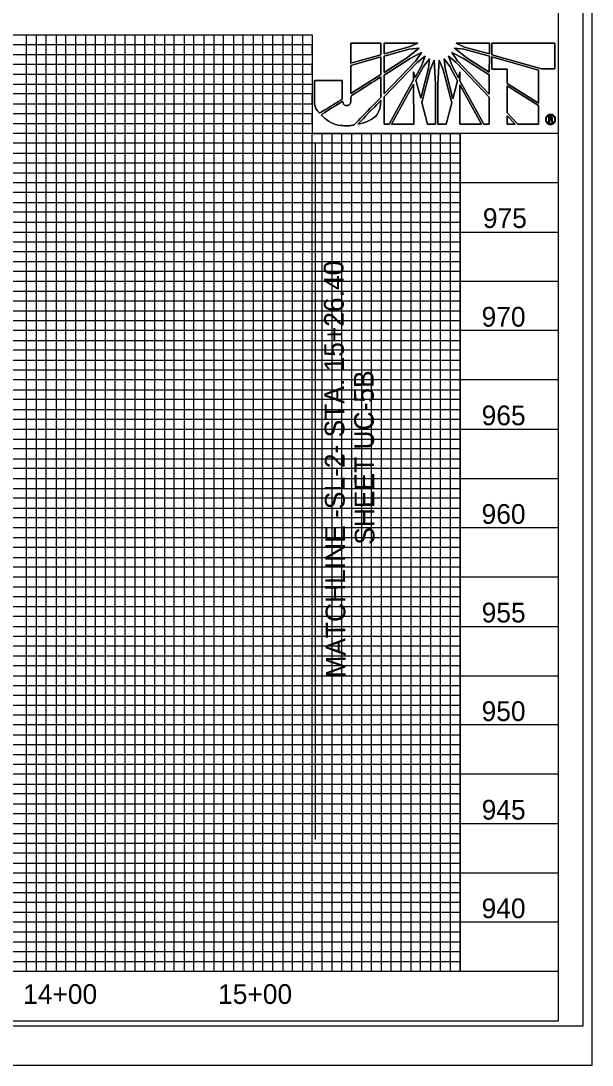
# Model space of a CAD drawing. Extents: x 0 to 2694, y -754 to 1499.
# Drawn here: x 2.35 to 2.833, y 0.008 to 0.891 of the extents above; entities that cross this region are included whole.
import ezdxf

# ---------------------------------------------------------------- set-up
doc = ezdxf.new("R2010")
doc.units = 0
for name, color, linetype in [('Layer 1', 7, 'Continuous'), ('Sheet Profile Grid Major CELL', 7, 'Continuous'), ('Sheet Profile Grid Middle', 7, 'Continuous'), ('Sheet Profile Grid Minor CELL', 7, 'Continuous'), ('UC Plan Profile Sheet 34 CELL', 7, 'Continuous'), ('UC Plan Sheet 34 CELL', 7, 'Continuous')]:
    doc.layers.add(name, color=color, linetype=linetype)

# ---------------------------------------------------------------- blocks, each defined once
blk = doc.blocks.new('block 2_1')
at = {"layer": 'Layer 1'}
for p, q in [((0.10682, 0.1325), (0.10682, 0.14026)), ((0.10682, 0.14026), (0.11852, 0.14026)), ((0.11852, 0.14026), (0.11852, 0.13575)), ((0.11973, 0.13613), (0.11973, 0.14032)), ((0.11973, 0.14032), (0.1329, 0.14032)), ((0.12954, 0.13884), (0.11973, 0.13613)), ((0.13337, 0.13839), (0.12852, 0.13445)), ((0.1329, 0.14032), (0.12954, 0.13884)), ((0.12954, 0.13793), (0.13337, 0.13839)), ((0.14715, 0.13839), (0.15076, 0.13793)), ((0.15206, 0.13438), (0.14715, 0.13839)), ((0.15109, 0.13878), (0.14781, 0.14032)), ((0.14781, 0.14032), (0.16078, 0.14026)), ((0.16078, 0.13606), (0.15109, 0.13878)), ((0.16078, 0.14026), (0.16078, 0.13606)), ((0.16169, 0.1358), (0.16169, 0.14032)), ((0.16169, 0.14032), (0.18629, 0.14032)), ((0.18629, 0.14032), (0.18629, 0.13024)), ((0.11852, 0.13575), (0.10682, 0.1325)), ((0.10682, 0.13161), (0.11852, 0.1349)), ((0.11852, 0.1349), (0.11852, 0.12812)), ((0.11973, 0.13523), (0.12954, 0.13793)), ((0.11973, 0.12889), (0.11973, 0.13523)), ((0.12852, 0.13445), (0.11973, 0.12889)), ((0.11973, 0.12787), (0.12987, 0.13432)), ((0.12987, 0.13432), (0.13433, 0.13658)), ((0.13433, 0.13658), (0.13207, 0.13341)), ((0.13257, 0.13277), (0.13568, 0.13517)), ((0.13568, 0.13517), (0.13425, 0.13142)), ((0.14476, 0.13517), (0.14787, 0.13277)), ((0.14619, 0.13142), (0.14476, 0.13517)), ((0.14613, 0.13658), (0.15065, 0.13432)), ((0.14839, 0.13335), (0.14613, 0.13658)), ((0.15065, 0.13432), (0.16071, 0.12793)), ((0.15076, 0.13793), (0.16078, 0.13517)), ((0.16071, 0.12897), (0.15206, 0.13438)), ((0.16078, 0.13517), (0.16071, 0.12897)), ((0.16169, 0.13567), (0.16169, 0.1358)), ((0.18106, 0.13024), (0.16169, 0.13567)), ((0.16169, 0.13497), (0.17982, 0.1298)), ((0.16169, 0.1349), (0.16169, 0.13497)), ((0.16169, 0.13019), (0.16169, 0.1349)), ((0.10682, 0.12071), (0.10682, 0.13161)), ((0.13207, 0.13341), (0.11973, 0.12057)), ((0.11973, 0.11933), (0.13257, 0.13277)), ((0.13425, 0.13142), (0.1318, 0.12696)), ((0.13213, 0.12586), (0.13505, 0.13115)), ((0.13704, 0.13051), (0.134, 0.11883)), ((0.13505, 0.13115), (0.13736, 0.13412)), ((0.13736, 0.13412), (0.13704, 0.13051)), ((0.13769, 0.12986), (0.13929, 0.1336)), ((0.13929, 0.1336), (0.1398, 0.12437)), ((0.14063, 0.12437), (0.14123, 0.1336)), ((0.14123, 0.1336), (0.14277, 0.12986)), ((0.1431, 0.13412), (0.14536, 0.13115)), ((0.14348, 0.13038), (0.1431, 0.13412)), ((0.14652, 0.11856), (0.14348, 0.13038)), ((0.14536, 0.13115), (0.14839, 0.12567)), ((0.1487, 0.12677), (0.14619, 0.13142)), ((0.14787, 0.13277), (0.16071, 0.11922)), ((0.16071, 0.12043), (0.14839, 0.13335)), ((0.1677, 0.13019), (0.16169, 0.13019)), ((0.1677, 0.12457), (0.1677, 0.13019)), ((0.18629, 0.13024), (0.18106, 0.13024)), ((0.11852, 0.12812), (0.10682, 0.12071)), ((0.11973, 0.12057), (0.11973, 0.12787)), ((0.1318, 0.12696), (0.13122, 0.12908)), ((0.13122, 0.12908), (0.13122, 0.126)), ((0.13439, 0.11721), (0.13769, 0.12986)), ((0.14277, 0.12986), (0.14613, 0.11702)), ((0.1493, 0.12908), (0.1487, 0.12677)), ((0.1493, 0.12567), (0.1493, 0.12908)), ((0.16071, 0.12793), (0.16071, 0.12043)), ((0.17982, 0.1298), (0.17982, 0.11688)), ((0.13122, 0.126), (0.12167, 0.10871)), ((0.12257, 0.10871), (0.13122, 0.12432)), ((0.13122, 0.12432), (0.1313, 0.10871)), ((0.134, 0.11883), (0.13213, 0.12586)), ((0.1398, 0.12437), (0.1398, 0.10877)), ((0.14063, 0.10877), (0.14063, 0.12437)), ((0.14839, 0.12567), (0.14652, 0.11856)), ((0.15864, 0.10871), (0.1493, 0.12567)), ((0.1493, 0.10877), (0.1493, 0.12399)), ((0.1493, 0.12399), (0.15768, 0.10877)), ((0.17982, 0.11688), (0.1677, 0.12457)), ((0.1677, 0.1236), (0.17982, 0.11597)), ((0.1677, 0.11314), (0.1677, 0.1236)), ((0.11973, 0.10871), (0.11973, 0.11933)), ((0.16071, 0.11922), (0.16071, 0.10871)), ((0.13659, 0.10877), (0.13439, 0.11721)), ((0.14613, 0.11702), (0.14387, 0.10877)), ((0.17982, 0.11597), (0.17982, 0.10871)), ((0.17189, 0.10871), (0.1677, 0.11314)), ((0.1677, 0.10871), (0.1677, 0.112)), ((0.1677, 0.112), (0.17073, 0.10871)), ((0.12167, 0.10871), (0.11973, 0.10871)), ((0.1313, 0.10871), (0.12257, 0.10871)), ((0.1398, 0.10877), (0.13659, 0.10877)), ((0.14387, 0.10877), (0.14063, 0.10877)), ((0.15768, 0.10877), (0.1493, 0.10877)), ((0.16071, 0.10871), (0.15864, 0.10871)), ((0.17073, 0.10871), (0.1677, 0.10871)), ((0.17982, 0.10871), (0.17189, 0.10871))]:
    blk.add_line(p, q, dxfattribs=at)
for points in [[(0.10682, 0.1325), (0.11852, 0.13575), (0.11852, 0.14026), (0.10682, 0.14026), (0.10682, 0.1325)], [(0.12954, 0.13884), (0.1329, 0.14032), (0.11973, 0.14032), (0.11973, 0.13613), (0.12954, 0.13884)], [(0.11973, 0.13523), (0.11973, 0.12889), (0.12852, 0.13445), (0.13337, 0.13839), (0.12954, 0.13793), (0.11973, 0.13523)], [(0.14715, 0.13839), (0.15206, 0.13438), (0.16071, 0.12897), (0.16078, 0.13517), (0.15076, 0.13793), (0.14715, 0.13839)], [(0.15109, 0.13878), (0.16078, 0.13606), (0.16078, 0.14026), (0.14781, 0.14032), (0.15109, 0.13878)], [(0.18629, 0.14032), (0.16169, 0.14032), (0.16169, 0.1358), (0.16169, 0.13567), (0.18106, 0.13024), (0.18629, 0.13024), (0.18629, 0.14032)], [(0.10682, 0.12071), (0.11852, 0.12812), (0.11852, 0.1349), (0.10682, 0.13161), (0.10682, 0.12071)], [(0.11973, 0.12787), (0.11973, 0.12057), (0.13207, 0.13341), (0.13433, 0.13658), (0.12987, 0.13432), (0.11973, 0.12787)], [(0.13568, 0.13517), (0.13257, 0.13277), (0.11973, 0.11933), (0.11973, 0.10871), (0.12167, 0.10871), (0.13122, 0.126), (0.13122, 0.12908), (0.1318, 0.12696), (0.13425, 0.13142), (0.13568, 0.13517)], [(0.14476, 0.13517), (0.14619, 0.13142), (0.1487, 0.12677), (0.1493, 0.12908), (0.1493, 0.12567), (0.15864, 0.10871), (0.16071, 0.10871), (0.16071, 0.11922), (0.14787, 0.13277), (0.14476, 0.13517)], [(0.14613, 0.13658), (0.14839, 0.13335), (0.16071, 0.12043), (0.16071, 0.12793), (0.15065, 0.13432), (0.14613, 0.13658)], [(0.16169, 0.13497), (0.16169, 0.1349), (0.16169, 0.13019), (0.1677, 0.13019), (0.1677, 0.12457), (0.17982, 0.11688), (0.17982, 0.1298), (0.16169, 0.13497)], [(0.13736, 0.13412), (0.13505, 0.13115), (0.13213, 0.12586), (0.134, 0.11883), (0.13704, 0.13051), (0.13736, 0.13412)], [(0.13769, 0.12986), (0.13439, 0.11721), (0.13659, 0.10877), (0.1398, 0.10877), (0.1398, 0.12437), (0.13929, 0.1336), (0.13769, 0.12986)], [(0.14123, 0.1336), (0.14063, 0.12437), (0.14063, 0.10877), (0.14387, 0.10877), (0.14613, 0.11702), (0.14277, 0.12986), (0.14123, 0.1336)], [(0.1431, 0.13412), (0.14348, 0.13038), (0.14652, 0.11856), (0.14839, 0.12567), (0.14536, 0.13115), (0.1431, 0.13412)], [(0.12257, 0.10871), (0.1313, 0.10871), (0.13122, 0.12432), (0.12257, 0.10871)], [(0.1493, 0.10877), (0.15768, 0.10877), (0.1493, 0.12399), (0.1493, 0.10877)], [(0.1677, 0.1236), (0.1677, 0.11314), (0.17189, 0.10871), (0.17982, 0.10871), (0.17982, 0.11597), (0.1677, 0.1236), (0.1677, 0.1236)], [(0.1677, 0.10871), (0.1677, 0.10871), (0.17073, 0.10871), (0.1677, 0.112), (0.1677, 0.10871)], [(0.18456, 0.11147), (0.18383, 0.11147), (0.18383, 0.10968), (0.18424, 0.10968), (0.18424, 0.11038), (0.18456, 0.11038), (0.18456, 0.1107), (0.18424, 0.1107), (0.18424, 0.11113), (0.18456, 0.11113), (0.18456, 0.11147)], [(0.18456, 0.11147), (0.18383, 0.11147), (0.18383, 0.10968), (0.18424, 0.10968), (0.18424, 0.11038), (0.18456, 0.11038)], [(0.18456, 0.1107), (0.18424, 0.1107), (0.18424, 0.11113), (0.18456, 0.11113)]]:
    blk.add_lwpolyline(points, dxfattribs=at)
for points in [[(0.10514, 0.11597), (0.10444, 0.11597), (0.10384, 0.11636), (0.10359, 0.11765), (0.10359, 0.11765), (0.09519, 0.11246), (0.09519, 0.11246), (0.09778, 0.10974), (0.10191, 0.10812), (0.10541, 0.10812), (0.10632, 0.10812), (0.10701, 0.10819), (0.10798, 0.10839), (0.10798, 0.10839), (0.11852, 0.11928), (0.11852, 0.11928), (0.11852, 0.11928), (0.11852, 0.12715), (0.11852, 0.12715), (0.11852, 0.12715), (0.10682, 0.11972), (0.10682, 0.11972), (0.10682, 0.11677), (0.1061, 0.11597), (0.10514, 0.11597)], [(0.10514, 0.11597), (0.1061, 0.11597), (0.10682, 0.11677), (0.10682, 0.11972), (0.10682, 0.11972), (0.11852, 0.12715), (0.11852, 0.12715), (0.11852, 0.12715), (0.11852, 0.11928), (0.11852, 0.11928), (0.11852, 0.11928), (0.10798, 0.10839), (0.10798, 0.10839), (0.10701, 0.10819), (0.10632, 0.10812), (0.10541, 0.10812), (0.10191, 0.10812), (0.09778, 0.10974), (0.09519, 0.11246), (0.09519, 0.11246), (0.10359, 0.11765), (0.10359, 0.11765), (0.10384, 0.11636), (0.10444, 0.11597), (0.10514, 0.11597)], [(0.10346, 0.12573), (0.10346, 0.12573), (0.09263, 0.12573), (0.09263, 0.12573), (0.09263, 0.12573), (0.09263, 0.11895), (0.09263, 0.11895), (0.09263, 0.11895), (0.09263, 0.11823), (0.09263, 0.11823), (0.09263, 0.11611), (0.09332, 0.11443), (0.09456, 0.11302), (0.09456, 0.11302), (0.10346, 0.11843), (0.10346, 0.11856), (0.10346, 0.11856), (0.10346, 0.12573), (0.10346, 0.12573)], [(0.10346, 0.12573), (0.10346, 0.12573), (0.10346, 0.11856), (0.10346, 0.11856), (0.10346, 0.11843), (0.09456, 0.11302), (0.09456, 0.11302), (0.09332, 0.11443), (0.09263, 0.11611), (0.09263, 0.11823), (0.09263, 0.11823), (0.09263, 0.11895), (0.09263, 0.11895), (0.09263, 0.11895), (0.09263, 0.12573), (0.09263, 0.12573), (0.09263, 0.12573), (0.10346, 0.12573), (0.10346, 0.12573)], [(0.11852, 0.11804), (0.11852, 0.11804), (0.1094, 0.10864), (0.1094, 0.10864), (0.11386, 0.10974), (0.11831, 0.11269), (0.11852, 0.11804)], [(0.11852, 0.11804), (0.11831, 0.11269), (0.11386, 0.10974), (0.1094, 0.10864), (0.1094, 0.10864), (0.11852, 0.11804), (0.11852, 0.11804)], [(0.18456, 0.10859), (0.18403, 0.10859), (0.18355, 0.10878), (0.18316, 0.10917), (0.18277, 0.10955), (0.18258, 0.11002), (0.18258, 0.11057), (0.18258, 0.11113), (0.18277, 0.1116), (0.18316, 0.11195), (0.18355, 0.11233), (0.18401, 0.11252), (0.18456, 0.11252), (0.18456, 0.11252), (0.18456, 0.11215), (0.18456, 0.11215), (0.18412, 0.11215), (0.18375, 0.112), (0.18344, 0.11171), (0.18313, 0.1114), (0.18297, 0.11101), (0.18297, 0.11057), (0.18297, 0.11013), (0.18313, 0.10974), (0.18344, 0.10943), (0.18375, 0.10913), (0.18412, 0.10898), (0.18456, 0.10898), (0.18456, 0.10898), (0.18456, 0.10859), (0.18456, 0.10859), (0.18456, 0.10859), (0.18456, 0.10859), (0.18456, 0.10859)], [(0.18456, 0.11252), (0.18401, 0.11252), (0.18355, 0.11233), (0.18316, 0.11195), (0.18277, 0.1116), (0.18258, 0.11113), (0.18258, 0.11057), (0.18258, 0.11002), (0.18277, 0.10955), (0.18316, 0.10917), (0.18355, 0.10878), (0.18403, 0.10859), (0.18456, 0.10859)], [(0.18456, 0.10898), (0.18412, 0.10898), (0.18375, 0.10913), (0.18344, 0.10943), (0.18313, 0.10974), (0.18297, 0.11013), (0.18297, 0.11057), (0.18297, 0.11101), (0.18313, 0.1114), (0.18344, 0.11171), (0.18375, 0.112), (0.18412, 0.11215), (0.18456, 0.11215)], [(0.18656, 0.11057), (0.18656, 0.11002), (0.18637, 0.10955), (0.18599, 0.10916), (0.1856, 0.10878), (0.18513, 0.10859), (0.18458, 0.10859), (0.18458, 0.10859), (0.18458, 0.10859), (0.18456, 0.10859), (0.18456, 0.10859), (0.18456, 0.10898), (0.18456, 0.10898), (0.18458, 0.10898), (0.18458, 0.10898), (0.18458, 0.10898), (0.18502, 0.10898), (0.18539, 0.10913), (0.1857, 0.10943), (0.18601, 0.10974), (0.18617, 0.11013), (0.18617, 0.11057), (0.18617, 0.11101), (0.18601, 0.1114), (0.1857, 0.11171), (0.18539, 0.112), (0.18502, 0.11215), (0.18456, 0.11215), (0.18456, 0.11215), (0.18456, 0.11252), (0.18456, 0.11252), (0.18512, 0.11252), (0.18559, 0.11233), (0.18598, 0.11195), (0.18637, 0.1116), (0.18656, 0.11113), (0.18656, 0.11057), (0.18656, 0.11057), (0.18656, 0.11057), (0.18656, 0.11057)], [(0.18656, 0.11057), (0.18656, 0.11113), (0.18637, 0.1116), (0.18598, 0.11195), (0.18559, 0.11233), (0.18512, 0.11252), (0.18456, 0.11252)], [(0.18456, 0.11215), (0.18502, 0.11215), (0.18539, 0.112), (0.1857, 0.11171), (0.18601, 0.1114), (0.18617, 0.11101), (0.18617, 0.11057), (0.18617, 0.11013), (0.18601, 0.10974), (0.1857, 0.10943), (0.18539, 0.10913), (0.18502, 0.10898), (0.18458, 0.10898), (0.18458, 0.10898), (0.18458, 0.10898), (0.18456, 0.10898)], [(0.18456, 0.11038), (0.18456, 0.11038), (0.18456, 0.1107), (0.18456, 0.1107), (0.18456, 0.1107), (0.18458, 0.1107), (0.18458, 0.1107), (0.18484, 0.1107), (0.18497, 0.11078), (0.18497, 0.11093), (0.18497, 0.11106), (0.18485, 0.11113), (0.18461, 0.11113), (0.18461, 0.11113), (0.18456, 0.11113), (0.18456, 0.11113), (0.18456, 0.11113), (0.18456, 0.11147), (0.18456, 0.11147), (0.18456, 0.11147), (0.18468, 0.11147), (0.18468, 0.11147), (0.18513, 0.11147), (0.18536, 0.11129), (0.18536, 0.11093), (0.18536, 0.11077), (0.18529, 0.11064), (0.18515, 0.11054), (0.18526, 0.11048), (0.18533, 0.11033), (0.18534, 0.1101), (0.18534, 0.1101), (0.18534, 0.11), (0.18534, 0.11), (0.18534, 0.11), (0.18536, 0.10994), (0.18536, 0.10994), (0.18536, 0.10994), (0.18536, 0.10987), (0.18536, 0.10987), (0.18536, 0.10987), (0.18541, 0.10968), (0.18541, 0.10968), (0.18541, 0.10968), (0.18503, 0.10968), (0.18503, 0.10968), (0.18499, 0.10978), (0.18495, 0.10987), (0.18495, 0.11), (0.18495, 0.11017), (0.18494, 0.11026), (0.18489, 0.11031), (0.18484, 0.11034), (0.18474, 0.11038), (0.18458, 0.11038), (0.18458, 0.11038), (0.18456, 0.11038), (0.18456, 0.11038)], [(0.18456, 0.11038), (0.18456, 0.11038), (0.18458, 0.11038), (0.18458, 0.11038), (0.18474, 0.11038), (0.18484, 0.11034), (0.18489, 0.11031), (0.18494, 0.11026), (0.18495, 0.11017), (0.18495, 0.11), (0.18495, 0.10987), (0.18499, 0.10978), (0.18503, 0.10968), (0.18503, 0.10968), (0.18541, 0.10968), (0.18541, 0.10968), (0.18541, 0.10968), (0.18536, 0.10987), (0.18536, 0.10987), (0.18536, 0.10987), (0.18536, 0.10994), (0.18536, 0.10994), (0.18536, 0.10994), (0.18534, 0.11), (0.18534, 0.11), (0.18534, 0.11), (0.18534, 0.1101), (0.18534, 0.1101), (0.18533, 0.11033), (0.18526, 0.11048), (0.18515, 0.11054), (0.18529, 0.11064), (0.18536, 0.11077), (0.18536, 0.11093), (0.18536, 0.11129), (0.18513, 0.11147), (0.18468, 0.11147), (0.18468, 0.11147), (0.18456, 0.11147), (0.18456, 0.11147)], [(0.18456, 0.11113), (0.18456, 0.11113), (0.18461, 0.11113), (0.18461, 0.11113), (0.18485, 0.11113), (0.18497, 0.11106), (0.18497, 0.11093), (0.18497, 0.11078), (0.18484, 0.1107), (0.18458, 0.1107), (0.18458, 0.1107), (0.18456, 0.1107), (0.18456, 0.1107)], [(0.18456, 0.10859), (0.18458, 0.10859), (0.18458, 0.10859), (0.18458, 0.10859), (0.18513, 0.10859), (0.1856, 0.10878), (0.18599, 0.10916), (0.18637, 0.10955), (0.18656, 0.11002), (0.18656, 0.11057)]]:
    blk.add_open_spline(points, degree=3, dxfattribs=at)

msp = doc.modelspace()

# ---------------------------------------------------------------- linework, layer by layer
at = {"layer": 'Sheet Profile Grid Major CELL'}
for points in [[(0.30499, 0.87916), (2.59666, 0.87916)], [(2.38833, 0.0875), (2.38833, 0.87916), (2.47166, 0.87916), (2.47166, 0.0875)], [(2.55499, 0.0875), (2.55499, 0.87916), (2.59666, 0.87916), (2.59666, 0.79583), (2.63833, 0.79583), (2.63833, 0.0875)], [(2.80499, 0.79583), (0.30499, 0.79583), (0.30499, 0.7125), (2.80499, 0.7125)], [(2.72166, 0.0875), (2.72166, 0.79583)], [(2.80499, 0.62916), (0.30499, 0.62916), (0.30499, 0.54583), (2.80499, 0.54583)], [(2.80499, 0.4625), (0.30499, 0.4625), (0.30499, 0.37916), (2.80499, 0.37916)], [(2.80499, 0.29583), (0.30499, 0.29583), (0.30499, 0.2125), (2.80499, 0.2125)], [(2.80499, 0.12916), (0.30499, 0.12916)]]:
    msp.add_lwpolyline(points, dxfattribs=at)
at = {"layer": 'Sheet Profile Grid Middle'}
for p, q in [((0.30499, 0.8375), (2.59666, 0.8375)), ((2.80499, 0.75416), (0.30499, 0.75416)), ((0.30499, 0.67083), (2.80499, 0.67083)), ((2.80499, 0.5875), (0.30499, 0.5875)), ((0.30499, 0.50416), (2.80499, 0.50416)), ((2.80499, 0.42083), (0.30499, 0.42083)), ((0.30499, 0.3375), (2.80499, 0.3375)), ((2.80499, 0.25416), (0.30499, 0.25416)), ((0.30499, 0.17083), (2.80499, 0.17083))]:
    msp.add_line(p, q, dxfattribs=at)
for points in [[(2.42999, 0.0875), (2.42999, 0.87916), (2.51333, 0.87916), (2.51333, 0.0875)], [(2.59666, 0.0875), (2.59666, 0.79583), (2.67999, 0.79583), (2.67999, 0.0875)]]:
    msp.add_lwpolyline(points, dxfattribs=at)
at = {"layer": 'Sheet Profile Grid Minor CELL'}
for points in [[(2.35499, 0.0875), (2.35499, 0.87916), (2.36333, 0.87916), (2.36333, 0.0875)], [(2.37166, 0.0875), (2.37166, 0.87916), (2.37999, 0.87916), (2.37999, 0.0875)], [(2.39666, 0.0875), (2.39666, 0.87916), (2.40499, 0.87916), (2.40499, 0.0875)], [(2.41333, 0.0875), (2.41333, 0.87916), (2.42166, 0.87916), (2.42166, 0.0875)], [(2.43833, 0.0875), (2.43833, 0.87916), (2.44666, 0.87916), (2.44666, 0.0875)], [(2.45499, 0.0875), (2.45499, 0.87916), (2.46333, 0.87916), (2.46333, 0.0875)], [(2.47999, 0.0875), (2.47999, 0.87916), (2.48833, 0.87916), (2.48833, 0.0875)], [(2.49666, 0.0875), (2.49666, 0.87916), (2.50499, 0.87916), (2.50499, 0.0875)], [(2.52166, 0.0875), (2.52166, 0.87916), (2.52999, 0.87916), (2.52999, 0.0875)], [(2.53833, 0.0875), (2.53833, 0.87916), (2.54666, 0.87916), (2.54666, 0.0875)], [(2.56333, 0.0875), (2.56333, 0.87916), (2.57166, 0.87916), (2.57166, 0.0875)], [(2.57999, 0.0875), (2.57999, 0.87916), (2.58833, 0.87916), (2.58833, 0.0875)], [(0.38833, 0.8625), (2.59666, 0.8625), (2.59666, 0.87083), (0.38833, 0.87083)], [(0.38833, 0.84583), (2.59666, 0.84583), (2.59666, 0.85416), (0.38833, 0.85416)], [(0.38833, 0.82083), (2.59666, 0.82083), (2.59666, 0.82916), (0.38833, 0.82916)], [(0.38833, 0.80416), (2.59666, 0.80416), (2.59666, 0.8125), (0.38833, 0.8125)], [(2.60499, 0.0875), (2.60499, 0.79583), (2.61333, 0.79583), (2.61333, 0.0875)], [(2.62166, 0.0875), (2.62166, 0.79583), (2.62999, 0.79583), (2.62999, 0.0875)], [(2.64666, 0.0875), (2.64666, 0.79583), (2.65499, 0.79583), (2.65499, 0.0875)], [(2.66333, 0.0875), (2.66333, 0.79583), (2.67166, 0.79583), (2.67166, 0.0875)], [(2.68833, 0.0875), (2.68833, 0.79583), (2.69666, 0.79583), (2.69666, 0.0875)], [(2.70499, 0.0875), (2.70499, 0.79583), (2.71333, 0.79583), (2.71333, 0.0875)], [(0.38833, 0.77916), (2.72166, 0.77916), (2.72166, 0.7875), (0.38833, 0.7875)], [(0.38833, 0.7625), (2.72166, 0.7625), (2.72166, 0.77083), (0.38833, 0.77083)], [(0.38833, 0.7375), (2.72166, 0.7375), (2.72166, 0.74583), (0.38833, 0.74583)], [(0.38833, 0.72083), (2.72166, 0.72083), (2.72166, 0.72916), (0.38833, 0.72916)], [(0.38833, 0.70416), (2.72166, 0.70416)], [(0.38833, 0.6875), (2.72166, 0.6875), (2.72166, 0.69583), (0.38833, 0.69583)], [(0.38833, 0.6625), (2.72166, 0.6625), (2.72166, 0.67916), (0.38833, 0.67916)], [(0.38833, 0.64583), (2.72166, 0.64583), (2.72166, 0.65416), (0.38833, 0.65416)], [(0.38833, 0.62083), (2.72166, 0.62083), (2.72166, 0.6375), (0.38833, 0.6375)], [(0.38833, 0.60416), (2.72166, 0.60416), (2.72166, 0.6125), (0.38833, 0.6125)], [(0.38833, 0.57916), (2.72166, 0.57916), (2.72166, 0.59583), (0.38833, 0.59583)], [(0.38833, 0.5625), (2.72166, 0.5625), (2.72166, 0.57083), (0.38833, 0.57083)], [(0.38833, 0.5375), (2.72166, 0.5375), (2.72166, 0.55416), (0.38833, 0.55416)], [(0.38833, 0.52083), (2.72166, 0.52083), (2.72166, 0.52916), (0.38833, 0.52916)], [(0.38833, 0.49583), (2.72166, 0.49583), (2.72166, 0.5125), (0.38833, 0.5125)], [(0.38833, 0.47916), (2.72166, 0.47916), (2.72166, 0.4875), (0.38833, 0.4875)], [(0.38833, 0.45416), (2.72166, 0.45416), (2.72166, 0.47083), (0.38833, 0.47083)], [(0.38833, 0.4375), (2.72166, 0.4375), (2.72166, 0.44583), (0.38833, 0.44583)], [(0.38833, 0.4125), (2.72166, 0.4125), (2.72166, 0.42916), (0.38833, 0.42916)], [(0.38833, 0.39583), (2.72166, 0.39583), (2.72166, 0.40416), (0.38833, 0.40416)], [(0.38833, 0.37083), (2.72166, 0.37083), (2.72166, 0.3875), (0.38833, 0.3875)], [(0.38833, 0.35416), (2.72166, 0.35416), (2.72166, 0.3625), (0.38833, 0.3625)], [(0.38833, 0.32916), (2.72166, 0.32916), (2.72166, 0.34583), (0.38833, 0.34583)], [(0.38833, 0.3125), (2.72166, 0.3125), (2.72166, 0.32083), (0.38833, 0.32083)], [(0.38833, 0.2875), (2.72166, 0.2875), (2.72166, 0.30416), (0.38833, 0.30416)], [(0.38833, 0.27083), (2.72166, 0.27083), (2.72166, 0.27916), (0.38833, 0.27916)], [(0.38833, 0.24583), (2.72166, 0.24583), (2.72166, 0.2625), (0.38833, 0.2625)], [(0.38833, 0.22916), (2.72166, 0.22916), (2.72166, 0.2375), (0.38833, 0.2375)], [(0.38833, 0.20416), (2.72166, 0.20416), (2.72166, 0.22083), (0.38833, 0.22083)], [(0.38833, 0.09583), (2.72166, 0.09583), (2.72166, 0.10416), (0.38833, 0.10416), (0.38833, 0.1125), (2.72166, 0.1125), (2.72166, 0.12083), (0.38833, 0.12083), (0.38833, 0.12916), (0.38833, 0.1375), (2.72166, 0.1375), (2.72166, 0.14583), (0.38833, 0.14583), (0.38833, 0.15416), (2.72166, 0.15416), (2.72166, 0.1625), (0.38833, 0.1625), (0.38833, 0.17083), (0.38833, 0.17916), (2.72166, 0.17916), (2.72166, 0.1875), (0.38833, 0.1875), (0.38833, 0.19583), (2.72166, 0.19583)]]:
    msp.add_lwpolyline(points, dxfattribs=at)
at = {"layer": 'UC Plan Profile Sheet 34 CELL'}
for p, q in [((2.59942, 0.19901), (2.59935, 0.78705)), ((2.80499, 0.0875), (0.30499, 0.0875))]:
    msp.add_line(p, q, dxfattribs=at)
for points in [[(0.02749, 0.00833), (2.83333, 0.00833), (2.83333, 1.83333), (0.02749, 1.83333)], [(0.04916, 0.04166), (2.82583, 0.04166), (2.82583, 1.8), (0.04916, 1.8)], [(2.80499, 1.79583), (0.30499, 1.79583), (0.30499, 0.04583), (2.80499, 0.04583)], [(0.38833, 0.87916), (2.59666, 0.87916), (2.59666, 0.79583), (2.72166, 0.79583), (2.72166, 0.0875), (0.38833, 0.0875)]]:
    msp.add_lwpolyline(points, close=True, dxfattribs=at)

# ---------------------------------------------------------------- block references
at = {"layer": 'UC Plan Sheet 34 CELL', "xscale": 2.170686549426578, "yscale": 2.170686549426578}
msp.add_blockref('block 2_1', (2.39752, 0.56763), dxfattribs=at)

# ---------------------------------------------------------------- texts
at = {"layer": 'UC Plan Profile Sheet 34 CELL'}
for s, p in [('975', (2.74093, 0.71593)), ('970', (2.73986, 0.63252)), ('965', (2.73993, 0.54918)), ('960', (2.73986, 0.46585)), ('955', (2.73993, 0.38252)), ('950', (2.73986, 0.29918)), ('945', (2.73993, 0.21585)), ('940', (2.73986, 0.13252)), ('14+00', (2.35221, 0.06004)), ('15+00', (2.51705, 0.06004))]:
    msp.add_text(s, height=0.016667, dxfattribs=at).set_placement(p)
for s, p in [('MATCHLINE -SL-2- STA. 15+26.40', (2.62494, 0.33588)), ('SHEET UC-5B', (2.64934, 0.44821))]:
    msp.add_text(s, height=0.0166667, rotation=90.30681, dxfattribs=at).set_placement(p)

doc.saveas('drawing.dxf')
